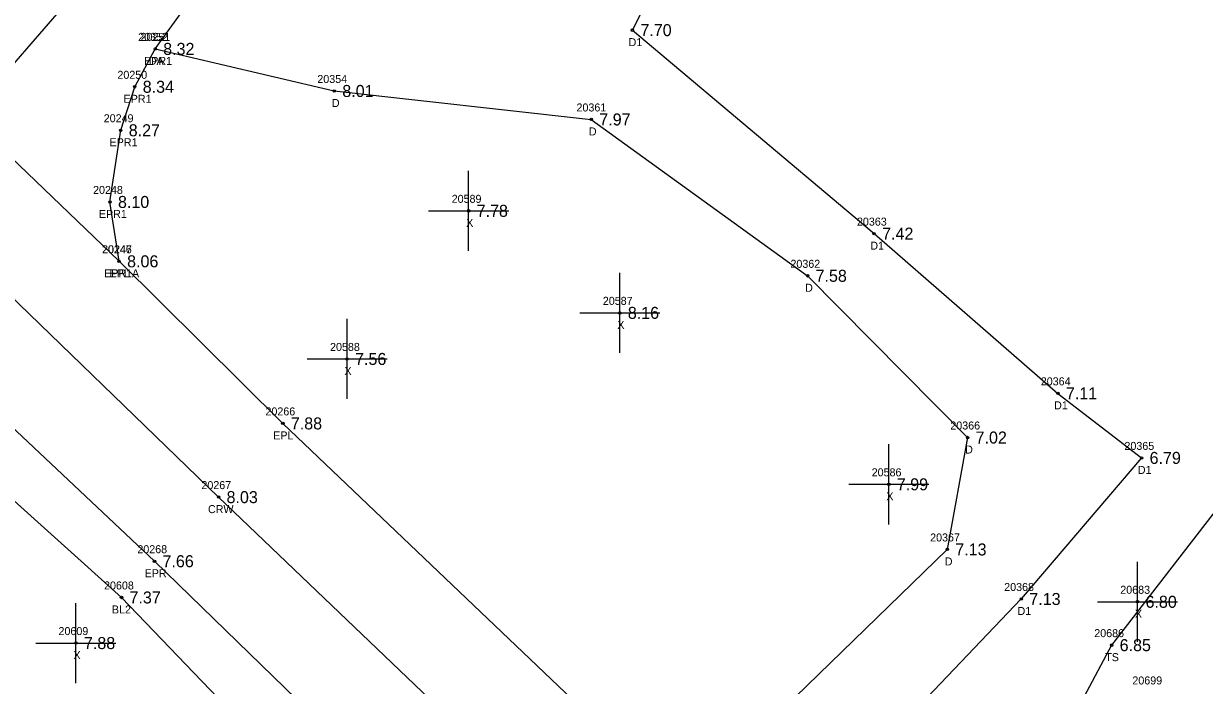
# Model space of a CAD drawing. Extents: x 2608745 to 2610333, y 641917 to 643463.
# Drawn here: x 2609084.1 to 2609231.6, y 643066.4 to 643149.1 of the extents above; entities that cross this region are included whole.
import ezdxf

# ---------------------------------------------------------------- set-up
doc = ezdxf.new("R2010")
doc.units = 0
for name, color, linetype in [('RD_DTM_BkLn1', 7, 'Continuous'), ('RD_DTM_BkLn2', 7, 'Continuous'), ('RD_DTM_BkLn_txCode', 7, 'Continuous'), ('RD_EX_Conc_txCode', 7, 'Continuous'), ('RD_EX_Driveway', 7, 'Continuous'), ('RD_EX_Driveway_txCode', 7, 'Continuous'), ('RD_EX_Misc', 7, 'Continuous'), ('RD_EX_Misc_txCode', 7, 'Continuous'), ('RD_EX_Road', 7, 'Continuous'), ('RD_EX_Road_txCode', 7, 'Continuous'), ('RD_EX_TX_Driveway_ELEV', 7, 'Continuous'), ('RD_EX_TX_Misc_ELEV', 7, 'Continuous'), ('RD_EX_TX_Road_ELEV', 7, 'Continuous'), ('RD_HC_Survey_ELEV', 7, 'Continuous'), ('RD_HC_Survey_txCode', 7, 'Continuous'), ('RD_SMD_Locator', 7, 'Continuous')]:
    doc.layers.add(name, color=color, linetype=linetype)

msp = doc.modelspace()

# ---------------------------------------------------------------- linework, layer by layer
at = {"layer": 'RD_DTM_BkLn1'}
for points in [[(2608814.73, 643373.65), (2608890.45, 643300.26), (2608962.19, 643231.31), (2609034.91, 643161.19), (2609108.48, 643089.9), (2609179.19, 643022.29), (2609255.71, 642948.78), (2609335.19, 642871.73), (2609410.7, 642798.48), (2609491.67, 642719.95), (2609518.07, 642695.15)], [(2609077.75, 643138.13), (2609090.47, 643152.84), (2609101.55, 643166.78), (2609119.24, 643191.44), (2609138.5, 643219.13), (2609195.83, 643301.54)], [(2609074.55, 643096.96), (2609096.36, 643077.36), (2609116.48, 643056.4)]]:
    msp.add_lwpolyline(points, dxfattribs=at)
at = {"layer": 'RD_DTM_BkLn2'}
msp.add_lwpolyline([(2609237.48, 643094.02), (2609220.03, 643071.4), (2609211.12, 643054.65), (2609205.92, 643044.31), (2609194.28, 643037.36), (2609184.97, 643038.02), (2609177.99, 643040.62)], dxfattribs=at)
at = {"layer": 'RD_EX_Driveway'}
for points in [[(2609166.46, 643161.04), (2609160.17, 643148.26), (2609190.36, 643122.83), (2609213.32, 643102.87), (2609223.77, 643094.8), (2609208.75, 643077.17), (2609183.58, 643050.78)], [(2609100.57, 643145.92), (2609122.94, 643140.66), (2609155.04, 643137.1), (2609182.05, 643117.56), (2609202.04, 643097.35), (2609199.5, 643083.36), (2609176.12, 643060.67)]]:
    msp.add_lwpolyline(points, dxfattribs=at)
at = {"layer": 'RD_EX_Misc'}
for p, q in [((2609139.72, 643120.68), (2609139.72, 643130.68)), ((2609134.72, 643125.68), (2609144.72, 643125.68)), ((2609158.6, 643107.93), (2609158.6, 643117.93)), ((2609124.53, 643102.17), (2609124.53, 643112.17)), ((2609153.6, 643112.93), (2609163.6, 643112.93)), ((2609119.53, 643107.17), (2609129.53, 643107.17)), ((2609192.2, 643086.5), (2609192.2, 643096.5)), ((2609187.2, 643091.5), (2609197.2, 643091.5)), ((2609223.26, 643071.82), (2609223.26, 643081.82)), ((2609090.67, 643066.66), (2609090.67, 643076.66)), ((2609218.26, 643076.82), (2609228.26, 643076.82)), ((2609085.67, 643071.66), (2609095.67, 643071.66))]:
    msp.add_line(p, q, dxfattribs=at)
at = {"layer": 'RD_EX_Road'}
for points in [[(2608806.89, 643364.99), (2608810.18, 643361.1), (2608820.75, 643351.25), (2608881.81, 643292.24), (2608917.83, 643257.49), (2608933.21, 643242.71), (2608954.07, 643222.83), (2609026.06, 643154.19), (2609039.6, 643139.96), (2609073.88, 643106.95), (2609100.48, 643081.89), (2609124.19, 643058.87), (2609171.61, 643013.71), (2609183.19, 643002.28), (2609197.91, 642988.37), (2609247.59, 642940.95), (2609328.02, 642863.6), (2609402.61, 642790.3), (2609474.23, 642720.69), (2609483.84, 642711.58), (2609495.78, 642699.92), (2609509.81, 642686.45)], [(2609096.06, 643119.37), (2609094.92, 643126.79), (2609096.26, 643135.75), (2609098.01, 643141.18), (2609100.57, 643145.92), (2609112.04, 643161.82), (2609127.63, 643184.43), (2609147.36, 643212.23), (2609204.42, 643294.94)], [(2609058.51, 643155.46), (2609096.06, 643119.37), (2609116.51, 643099.11), (2609162.4, 643055.35), (2609177.21, 643041.34), (2609188.35, 643030.96), (2609199.91, 643019.76), (2609205.8, 643014.04), (2609217.13, 643003.17), (2609235.83, 642983.9), (2609237.03, 642983.51), (2609256.8, 642965.04), (2609258.49, 642962.51), (2609263.65, 642957.66), (2609344.71, 642879.89), (2609418.83, 642806.19), (2609500.61, 642728.46), (2609512.38, 642716.82), (2609526.19, 642703.5)]]:
    msp.add_lwpolyline(points, dxfattribs=at)
at = {"layer": 'RD_SMD_Locator'}
for centre in [(2609160.17, 643148.26), (2609100.57, 643145.92), (2609100.57, 643145.92), (2609098.01, 643141.18), (2609122.94, 643140.66), (2609155.04, 643137.1), (2609096.26, 643135.75), (2609094.92, 643126.79), (2609139.72, 643125.68), (2609190.36, 643122.83), (2609096.06, 643119.37), (2609096.06, 643119.37), (2609182.05, 643117.56), (2609158.6, 643112.93), (2609124.53, 643107.17), (2609213.32, 643102.87), (2609116.51, 643099.11), (2609202.04, 643097.35), (2609223.77, 643094.8), (2609192.2, 643091.5), (2609108.48, 643089.9), (2609199.5, 643083.36), (2609100.48, 643081.89), (2609096.36, 643077.36), (2609208.75, 643077.17), (2609223.26, 643076.82), (2609090.67, 643071.66), (2609220.03, 643071.4)]:
    msp.add_circle(centre, 0.15, dxfattribs=at)

# ---------------------------------------------------------------- texts
at = {"layer": 'RD_DTM_BkLn_txCode'}
for s, p in [('20608', (2609094.18, 643078.36)), ('BL2', (2609095.16, 643075.36)), ('20686', (2609217.86, 643072.4)), ('TS', (2609219.23, 643069.4))]:
    msp.add_text(s, height=1, dxfattribs=at).set_placement(p)
at = {"layer": 'RD_EX_Conc_txCode'}
msp.add_text('20699', height=1, dxfattribs=at).set_placement((2609222.62, 643066.49))
at = {"layer": 'RD_EX_Driveway_txCode'}
for s, p in [('20352', (2609098.45, 643146.92)), ('D1', (2609159.7, 643146.26)), ('DA', (2609099.77, 643143.92)), ('20354', (2609120.82, 643141.66)), ('D', (2609122.63, 643138.66)), ('20361', (2609153.19, 643138.1)), ('D', (2609154.74, 643135.1)), ('20363', (2609188.22, 643123.83)), ('D1', (2609189.89, 643120.83)), ('20362', (2609179.91, 643118.56)), ('D', (2609181.74, 643115.56)), ('20364', (2609211.18, 643103.87)), ('D1', (2609212.84, 643100.87)), ('20366', (2609199.88, 643098.35)), ('D', (2609201.73, 643095.35)), ('20365', (2609221.63, 643095.8)), ('D1', (2609223.3, 643092.8)), ('20367', (2609197.36, 643084.36)), ('D', (2609199.19, 643081.36)), ('20368', (2609206.61, 643078.17)), ('D1', (2609208.28, 643075.17))]:
    msp.add_text(s, height=1, dxfattribs=at).set_placement(p)
at = {"layer": 'RD_EX_Misc_txCode'}
for s, p in [('20589', (2609137.6, 643126.68)), ('X', (2609139.41, 643123.68)), ('20587', (2609156.48, 643113.93)), ('X', (2609158.29, 643110.93)), ('20588', (2609122.41, 643108.17)), ('X', (2609124.21, 643105.17)), ('20586', (2609190.06, 643092.5)), ('X', (2609191.89, 643089.5)), ('20683', (2609221.11, 643077.82)), ('X', (2609222.94, 643074.82)), ('20609', (2609088.49, 643072.66)), ('X', (2609090.36, 643069.66))]:
    msp.add_text(s, height=1, dxfattribs=at).set_placement(p)
at = {"layer": 'RD_EX_Road_txCode'}
for s, p in [('20251', (2609098.73, 643146.92)), ('EPR1', (2609099.18, 643143.92)), ('20250', (2609095.85, 643142.18)), ('EPR1', (2609096.62, 643139.18)), ('20249', (2609094.14, 643136.75)), ('EPR1', (2609094.87, 643133.75)), ('20248', (2609092.81, 643127.79)), ('EPR1', (2609093.53, 643124.79)), ('20246', (2609093.92, 643120.37)), ('20247', (2609093.94, 643120.37)), ('EPR1A', (2609094.18, 643117.37)), ('EPL', (2609094.86, 643117.37)), ('20266', (2609114.34, 643100.11)), ('EPL', (2609115.31, 643097.11)), ('20268', (2609098.34, 643082.89)), ('EPR', (2609099.25, 643079.89))]:
    msp.add_text(s, height=1, dxfattribs=at).set_placement(p)
at = {"layer": 'RD_EX_TX_Driveway_ELEV'}
for s, p in [('7.70', (2609161.17, 643147.51)), ('8.32', (2609101.57, 643145.17)), ('8.01', (2609123.94, 643139.91)), ('7.97', (2609156.04, 643136.35)), ('7.42', (2609191.36, 643122.08)), ('7.58', (2609183.05, 643116.81)), ('7.11', (2609214.32, 643102.12)), ('7.02', (2609203.04, 643096.6)), ('6.79', (2609224.77, 643094.05)), ('7.13', (2609200.5, 643082.61)), ('7.13', (2609209.75, 643076.42))]:
    msp.add_text(s, height=1.5, dxfattribs=at).set_placement(p)
at = {"layer": 'RD_EX_TX_Misc_ELEV'}
for s, p in [('7.78', (2609140.72, 643124.93)), ('8.16', (2609159.6, 643112.18)), ('7.56', (2609125.53, 643106.42)), ('7.99', (2609193.2, 643090.75)), ('7.37', (2609097.36, 643076.61)), ('6.80', (2609224.26, 643076.07)), ('7.88', (2609091.67, 643070.91)), ('6.85', (2609221.03, 643070.65))]:
    msp.add_text(s, height=1.5, dxfattribs=at).set_placement(p)
at = {"layer": 'RD_EX_TX_Road_ELEV'}
for s, p in [('8.32', (2609101.57, 643145.17)), ('8.34', (2609099.01, 643140.43)), ('8.27', (2609097.26, 643135)), ('8.10', (2609095.92, 643126.04)), ('8.06', (2609097.06, 643118.62)), ('8.06', (2609097.06, 643118.62)), ('7.88', (2609117.51, 643098.36)), ('7.66', (2609101.48, 643081.14))]:
    msp.add_text(s, height=1.5, dxfattribs=at).set_placement(p)
at = {"layer": 'RD_HC_Survey_ELEV'}
msp.add_text('8.03', height=1.5, dxfattribs=at).set_placement((2609109.48, 643089.15))
at = {"layer": 'RD_HC_Survey_txCode'}
for s, p in [('20267', (2609106.34, 643090.9)), ('CRW', (2609107.16, 643087.9))]:
    msp.add_text(s, height=1, dxfattribs=at).set_placement(p)

doc.saveas('drawing.dxf')
